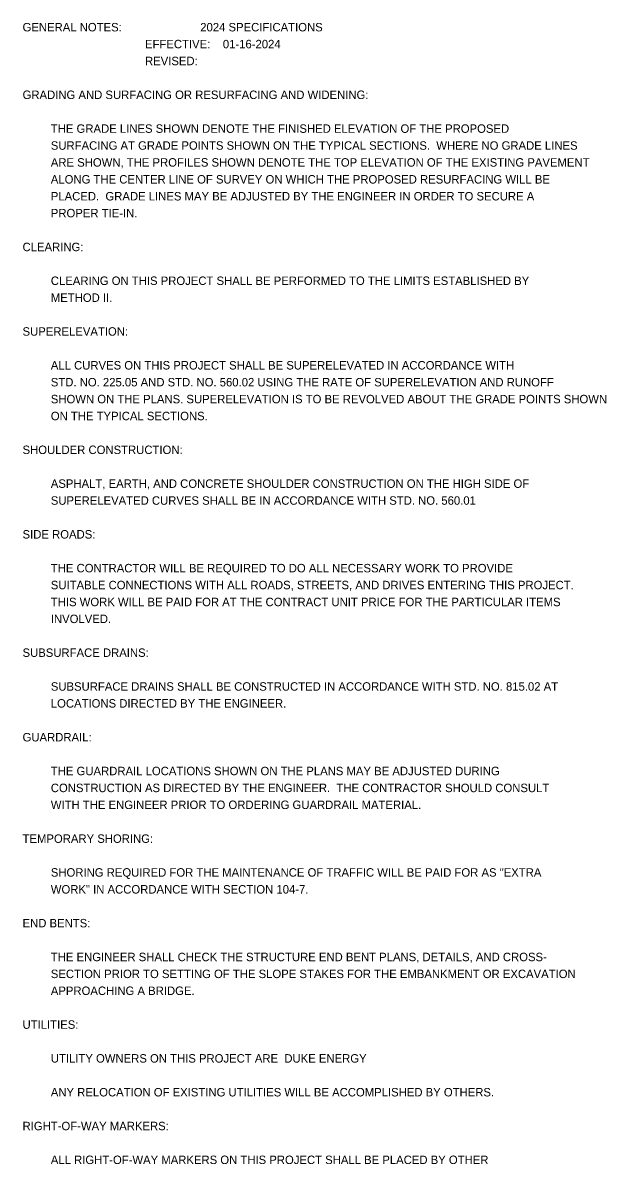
# Model space of a CAD drawing. Extents: x 1844369 to 1844800, y 671424 to 671721.
# Drawn here: x 1844475.3 to 1844501.5, y 671423.6 to 671474.9 of the extents above; entities that cross this region are included whole.
import ezdxf

# ---------------------------------------------------------------- set-up
doc = ezdxf.new("R2010")
doc.units = 0
doc.layers.add('Sheet Data Text CELL', color=7, linetype='Continuous')

msp = doc.modelspace()

# ---------------------------------------------------------------- texts
at = {"layer": 'Sheet Data Text CELL'}
for s, p in [('GENERAL NOTES:                         2024 SPECIFICATIONS', (1844475.276, 671474.549)), ('                                       EFFECTIVE:    01-16-2024', (1844475.276, 671473.789)), ('                                       REVISED:      ', (1844475.276, 671473.029)), ('GRADING AND SURFACING OR RESURFACING AND WIDENING:  ', (1844475.276, 671471.509)), ('         THE GRADE LINES SHOWN DENOTE THE FINISHED ELEVATION OF THE PROPOSED ', (1844475.276, 671469.989)), ('         SURFACING AT GRADE POINTS SHOWN ON THE TYPICAL SECTIONS.  WHERE NO GRADE LINES ', (1844475.276, 671469.229)), ('         ARE SHOWN, THE PROFILES SHOWN DENOTE THE TOP ELEVATION OF THE EXISTING PAVEMENT ', (1844475.276, 671468.469)), ('         ALONG THE CENTER LINE OF SURVEY ON WHICH THE PROPOSED RESURFACING WILL BE ', (1844475.276, 671467.709)), ('         PLACED.  GRADE LINES MAY BE ADJUSTED BY THE ENGINEER IN ORDER TO SECURE A ', (1844475.276, 671466.949)), ('         PROPER TIE-IN.  ', (1844475.276, 671466.189)), ('CLEARING:  ', (1844475.276, 671464.669)), ('         CLEARING ON THIS PROJECT SHALL BE PERFORMED TO THE LIMITS ESTABLISHED BY ', (1844475.276, 671463.149)), ('         METHOD II.', (1844475.276, 671462.389)), ('SUPERELEVATION:  ', (1844475.276, 671460.869)), ('         ALL CURVES ON THIS PROJECT SHALL BE SUPERELEVATED IN ACCORDANCE WITH', (1844475.276, 671459.349)), ('         STD. NO. 225.05 AND STD. NO. 560.02 USING THE RATE OF SUPERELEVATION AND RUNOFF', (1844475.276, 671458.589)), ('         SHOWN ON THE PLANS. SUPERELEVATION IS TO BE REVOLVED ABOUT THE GRADE POINTS SHOWN', (1844475.276, 671457.829)), ('         ON THE TYPICAL SECTIONS.  ', (1844475.276, 671457.069)), ('SHOULDER CONSTRUCTION:  ', (1844475.276, 671455.549)), ('         ASPHALT, EARTH, AND CONCRETE SHOULDER CONSTRUCTION ON THE HIGH SIDE OF', (1844475.276, 671454.029)), ('         SUPERELEVATED CURVES SHALL BE IN ACCORDANCE WITH STD. NO. 560.01', (1844475.276, 671453.269)), ('SIDE ROADS:  ', (1844475.276, 671451.749)), ('         THE CONTRACTOR WILL BE REQUIRED TO DO ALL NECESSARY WORK TO PROVIDE ', (1844475.276, 671450.229)), ('         SUITABLE CONNECTIONS WITH ALL ROADS, STREETS, AND DRIVES ENTERING THIS PROJECT.  ', (1844475.276, 671449.469)), ('         THIS WORK WILL BE PAID FOR AT THE CONTRACT UNIT PRICE FOR THE PARTICULAR ITEMS ', (1844475.276, 671448.709)), ('         INVOLVED.  ', (1844475.276, 671447.949)), ('SUBSURFACE DRAINS:', (1844475.276, 671446.429)), ('         SUBSURFACE DRAINS SHALL BE CONSTRUCTED IN ACCORDANCE WITH STD. NO. 815.02 AT ', (1844475.276, 671444.909)), ('         LOCATIONS DIRECTED BY THE ENGINEER.  ', (1844475.276, 671444.149)), ('GUARDRAIL:  ', (1844475.276, 671442.629)), ('         THE GUARDRAIL LOCATIONS SHOWN ON THE PLANS MAY BE ADJUSTED DURING ', (1844475.276, 671441.109)), ('         CONSTRUCTION AS DIRECTED BY THE ENGINEER.  THE CONTRACTOR SHOULD CONSULT', (1844475.276, 671440.349)), ('         WITH THE ENGINEER PRIOR TO ORDERING GUARDRAIL MATERIAL.', (1844475.276, 671439.589)), ('TEMPORARY SHORING:  ', (1844475.276, 671438.069)), ('         SHORING REQUIRED FOR THE MAINTENANCE OF TRAFFIC WILL BE PAID FOR AS "EXTRA ', (1844475.276, 671436.549)), ('         WORK" IN ACCORDANCE WITH SECTION 104-7.  ', (1844475.276, 671435.789)), ('END BENTS:  ', (1844475.276, 671434.269)), ('         THE ENGINEER SHALL CHECK THE STRUCTURE END BENT PLANS, DETAILS, AND CROSS-', (1844475.276, 671432.749)), ('         SECTION PRIOR TO SETTING OF THE SLOPE STAKES FOR THE EMBANKMENT OR EXCAVATION ', (1844475.276, 671431.989)), ('         APPROACHING A BRIDGE.  ', (1844475.276, 671431.229)), ('UTILITIES:  ', (1844475.276, 671429.709)), ('         UTILITY OWNERS ON THIS PROJECT ARE  DUKE ENERGY', (1844475.276, 671428.189)), ('         ANY RELOCATION OF EXISTING UTILITIES WILL BE ACCOMPLISHED BY OTHERS.  ', (1844475.276, 671426.669)), ('RIGHT-OF-WAY MARKERS:  ', (1844475.276, 671425.149)), ('         ALL RIGHT-OF-WAY MARKERS ON THIS PROJECT SHALL BE PLACED BY OTHER', (1844475.276, 671423.629))]:
    msp.add_text(s, height=0.38, dxfattribs=at).set_placement(p)

doc.saveas('drawing.dxf')
